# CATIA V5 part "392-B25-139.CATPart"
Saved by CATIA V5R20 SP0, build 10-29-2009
Part number: 392-B25-139
Definition: NONE
Nomenclature: 392-B25-139
Source: Unknown
Description: 392-B25-139
Bounding box of the stored display mesh (mm): x 0 to 139, y -12.356 to 12.356, z -12.25 to 12.064
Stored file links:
  C:\Users\Utente\Desktop\IO LAVORO\3D X SITO CF\X SITO\3D files 392B\392-B25-139.CATPart
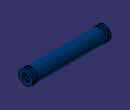
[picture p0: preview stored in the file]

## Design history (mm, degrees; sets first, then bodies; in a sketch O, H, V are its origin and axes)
Body1 "392-B25-139" (main body)
  Solid1: solid without history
